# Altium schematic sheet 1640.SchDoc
size A2
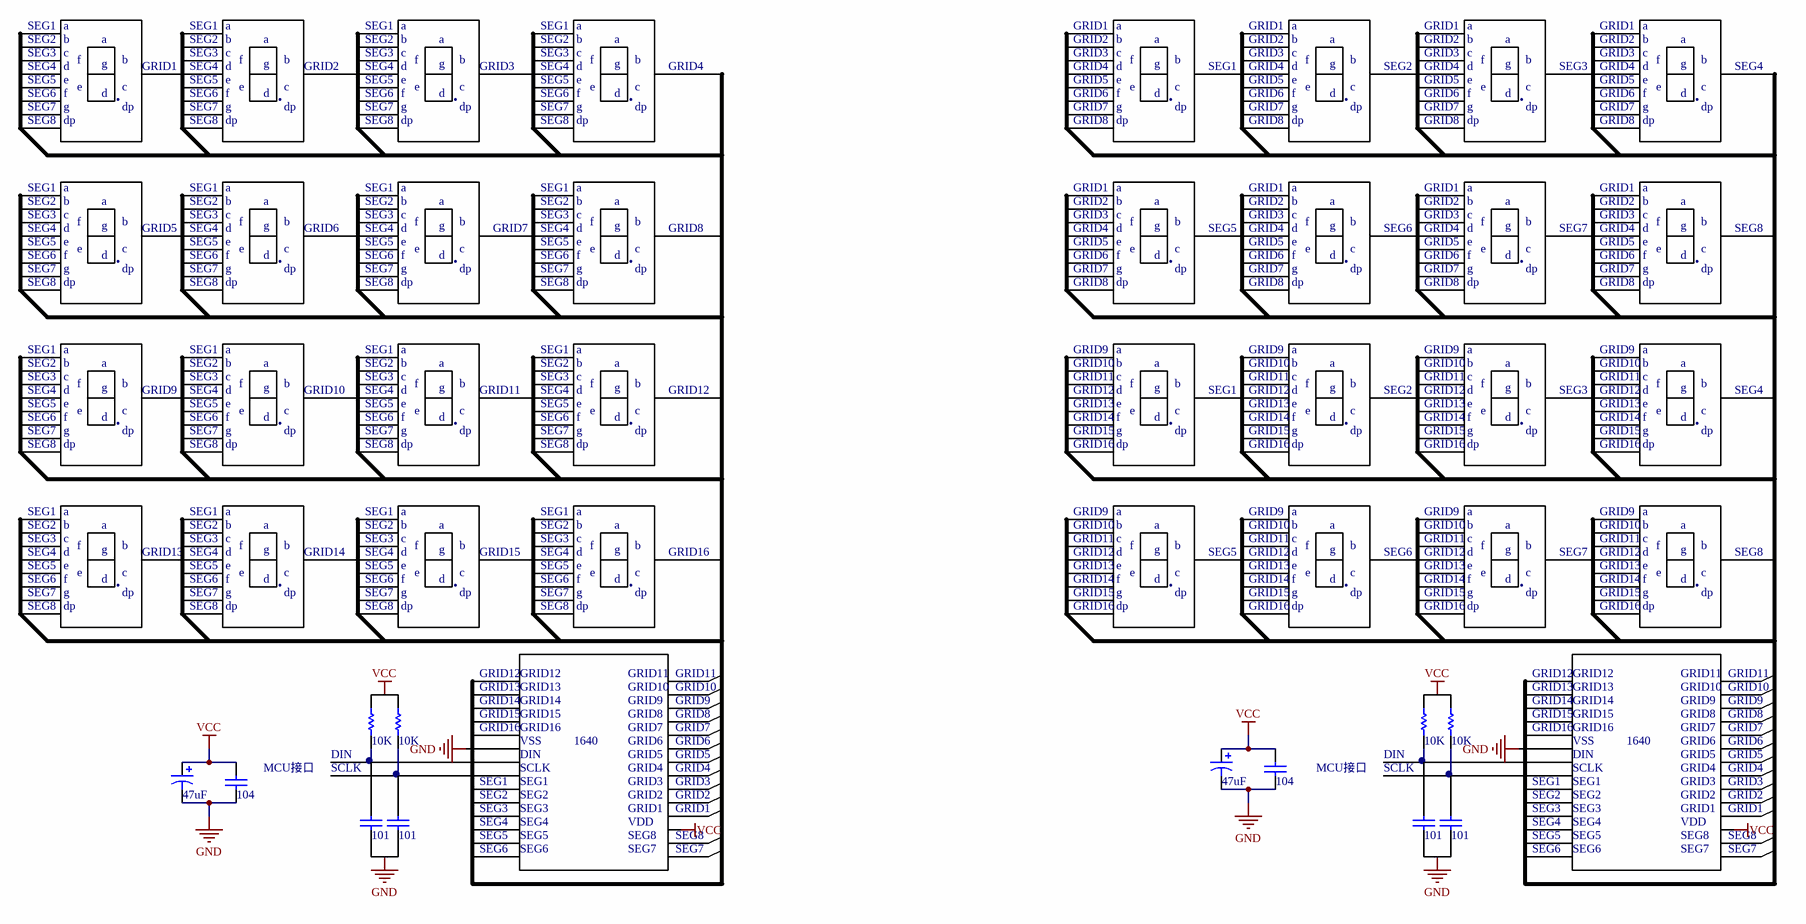
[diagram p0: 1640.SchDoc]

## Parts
(Parts that share a designator on the sheet are numbered #1, #2 ... from top to bottom, then left to right.)
C?#1  value 47uF  [RB7.6-15]  (hidden comment: Cap Pol1)
C?#2  value 47uF  [RB7.6-15]  (hidden comment: Cap Pol1)
C?#3  value 104  [RAD-0.3]  (hidden comment: Cap)
C?#4  value 104  [RAD-0.3]  (hidden comment: Cap)
C?#5  value 101  [RAD-0.3]  (hidden comment: Cap)
C?#6  value 101  [RAD-0.3]  (hidden comment: Cap)
C?#7  value 101  [RAD-0.3]  (hidden comment: Cap)
C?#8  value 101  [RAD-0.3]  (hidden comment: Cap)
R?#1  value 10K  [AXIAL-0.3]  (hidden comment: Res1)
R?#2  value 10K  [AXIAL-0.3]  (hidden comment: Res1)
R?#3  value 10K  [AXIAL-0.3]  (hidden comment: Res1)
R?#4  value 10K  [AXIAL-0.3]  (hidden comment: Res1)

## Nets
GND: C?#1.2 C?#2.2 C?#3.1 C?#4.1
VCC: C?#1.1 C?#2.1 C?#3.2 C?#4.2

Not connected (* = marked no-connect by the designer): C?#5 1 2; C?#6 1 2; C?#7 1 2; C?#8 1 2; R?#1 1 2; R?#2 1 2; R?#3 1 2; R?#4 1 2

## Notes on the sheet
- SEG1
- SEG2
- SEG3
- SEG4
- a
- b
- c
- d
- f
- g
- GRID1
- GRID2
- GRID3
- GRID4
- SEG5
- SEG6
- SEG7
- SEG8
- e
- dp
- ·
- GRID5
- GRID7
- GRID6
- GRID8
- GRID9
- GRID10
- GRID11
- GRID12
- GRID13
- GRID15
- GRID14
- GRID16
- VSS
- 1640
- (near C?#4) MCU接口
- (near R?#1) DIN
- SCLK
- (near R?#1) ·
- DIN
- (near C?#3) MCU接口
- (near R?#3) DIN
- (near R?#3) ·
- VDD
- Labels drawn without touching a wire or pin: GND, VCC

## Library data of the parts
C?#1 C?#2 = Cap Pol1: Polarized Capacitor (Radial)
C?#3-C?#8 = Cap: Capacitor
R?#1-R?#4 = Res1: Resistor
